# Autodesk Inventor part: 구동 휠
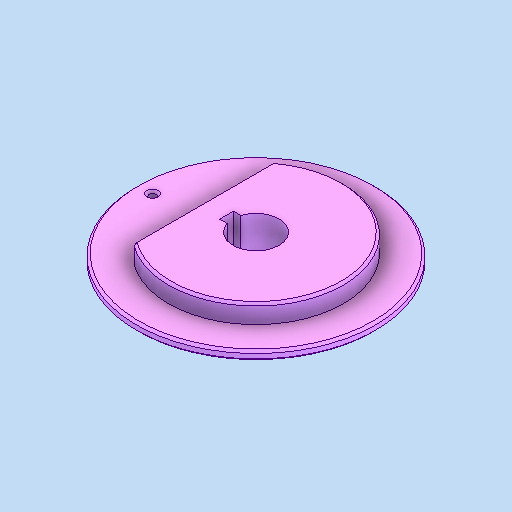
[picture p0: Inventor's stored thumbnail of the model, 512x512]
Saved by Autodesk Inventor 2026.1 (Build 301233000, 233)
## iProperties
Created: 2025-09
Part Number: 구동 휠
Material: 강철, 연강
Document SubType Name: Modeling
Designer: PC-30
Density: 7.85 g/cm^3
Appearance: 기본값
Author: jhkim
Sending System: Autodesk Inventor 2026
Preprocessor: ST-DEVELOPER v20.1
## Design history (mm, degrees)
feature "솔리드1"
node "솔리드2"
